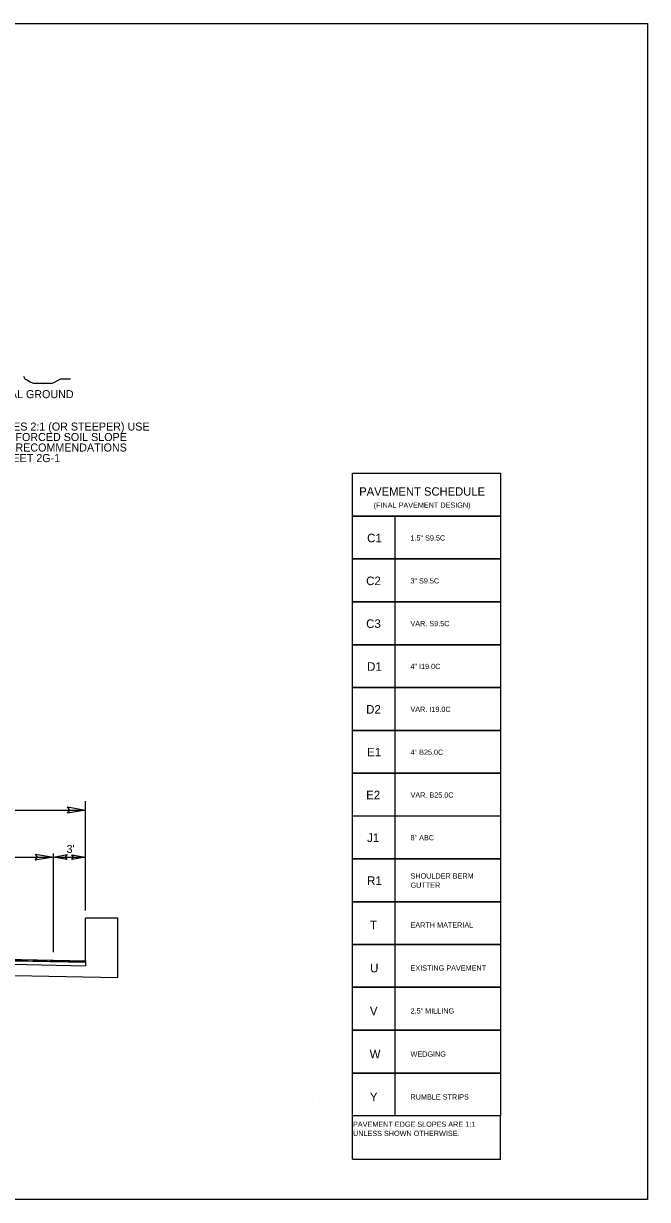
# Model space of a CAD drawing. Extents: x 1548135 to 1549339, y 868664 to 869085.
# Drawn here: x 1548246.7 to 1548305, y 868664.3 to 868774.3 of the extents above; entities that cross this region are included whole.
import ezdxf

# ---------------------------------------------------------------- set-up
doc = ezdxf.new("R2010")
doc.units = 0
for name, color, linetype in [('Default', 7, 'Continuous'), ('P_RDY_TC_Pvmt_Asphalt_Base_Course', 7, 'Continuous'), ('Prop Dimension', 7, 'Continuous'), ('Prop Terminator CELL', 7, 'Continuous'), ('Sheet_Data_Field_CELL', 7, 'Continuous'), ('Typical Grade Point Symbol CELL', 7, 'Continuous'), ('Typical Hinge Slope Interstate CELL', 7, 'Continuous'), ('Typical Shoulder Slope CELL', 7, 'Continuous'), ('Typical Text Grade Point CELL', 7, 'Continuous'), ('Typical Text ID Circle CELL', 7, 'Continuous')]:
    doc.layers.add(name, color=color, linetype=linetype)

msp = doc.modelspace()

# ---------------------------------------------------------------- linework, layer by layer
at = {"layer": 'Default'}
msp.add_lwpolyline([(1548135.05, 868774.32), (1548305.05, 868774.32), (1548305.05, 868664.32), (1548135.05, 868664.32)], close=True, dxfattribs=at)
at = {"layer": 'P_RDY_TC_Pvmt_Asphalt_Base_Course'}
for points in [[(1548250.81, 868701.04), (1548252.5, 868700.75), (1548250.8, 868700.45), (1548251.02, 868700.75)], [(1548247.8, 868696.64), (1548249.49, 868696.35), (1548247.79, 868696.05), (1548248.01, 868696.35)], [(1548250.75, 868696.13), (1548249.49, 868696.35), (1548250.76, 868696.58), (1548250.6, 868696.35)], [(1548251.22, 868696.57), (1548252.49, 868696.35), (1548251.22, 868696.13), (1548251.38, 868696.35)]]:
    msp.add_lwpolyline(points, close=True, dxfattribs=at)
at = {"layer": 'Prop Dimension'}
msp.add_lwpolyline([(1548246.68, 868741.34), (1548246.81, 868741.08), (1548247.07, 868740.95), (1548247.33, 868740.82), (1548247.59, 868740.69), (1548247.85, 868740.69), (1548248.11, 868740.69), (1548248.37, 868740.69), (1548248.63, 868740.69), (1548248.89, 868740.69), (1548249.15, 868740.69), (1548249.41, 868740.69), (1548249.66, 868740.82), (1548249.92, 868740.95), (1548250.18, 868741.08), (1548250.57, 868741.08), (1548250.83, 868741.08), (1548251.09, 868741.08)], dxfattribs=at)
at = {"layer": 'Prop Terminator CELL'}
msp.add_lwpolyline([(1548222.49, 868686.65), (1548237.49, 868686.95), (1548252.49, 868686.65), (1548252.49, 868686.52), (1548247.13, 868686.63), (1548245.81, 868686.66), (1548243.62, 868686.7), (1548237.49, 868686.82), (1548237.49, 868686.82), (1548226.43, 868686.6), (1548222.49, 868686.52)], close=True, dxfattribs=at)
at = {"layer": 'Typical Grade Point Symbol CELL'}
for p, q in [((1548252.49, 868691.35), (1548252.49, 868701.58)), ((1548237.49, 868700.75), (1548252.49, 868700.75)), ((1548249.49, 868687.47), (1548249.49, 868696.7)), ((1548237.49, 868696.35), (1548252.49, 868696.35)), ((1548250.49, 868696.35), (1548252.49, 868696.35))]:
    msp.add_line(p, q, dxfattribs=at)
at = {"layer": 'Typical Hinge Slope Interstate CELL'}
for p, q in [((1548273.7, 868673.74), (1548273.7, 868673.74)), ((1548277.45, 868669.06), (1548277.45, 868672.16)), ((1548277.45, 868668.11), (1548277.45, 868672.12)), ((1548291.3, 868668.07), (1548291.3, 868672.12)), ((1548281.46, 868668.07), (1548277.45, 868668.07)), ((1548291.3, 868668.07), (1548281.46, 868668.07))]:
    msp.add_line(p, q, dxfattribs=at)
msp.add_lwpolyline([(1548277.45, 868732.25), (1548291.29, 868732.25), (1548291.29, 868728.25), (1548277.45, 868728.25)], close=True, dxfattribs=at)
for points in [[(1548281.45, 868724.24), (1548277.45, 868724.24), (1548277.45, 868728.25), (1548291.29, 868728.25), (1548291.29, 868724.24), (1548281.45, 868724.24), (1548281.45, 868728.25)], [(1548281.45, 868720.23), (1548277.45, 868720.23), (1548277.45, 868724.24), (1548291.29, 868724.24), (1548291.29, 868720.23), (1548281.45, 868720.23), (1548281.45, 868724.24)], [(1548281.46, 868716.22), (1548277.45, 868716.22), (1548277.45, 868720.23), (1548291.29, 868720.23), (1548291.29, 868716.22), (1548281.46, 868716.22), (1548281.46, 868720.23)], [(1548281.46, 868712.21), (1548277.45, 868712.21), (1548277.45, 868716.22), (1548291.29, 868716.22), (1548291.29, 868712.21), (1548281.46, 868712.21), (1548281.46, 868716.22)], [(1548281.46, 868708.2), (1548277.45, 868708.2), (1548277.45, 868712.21), (1548291.29, 868712.21), (1548291.29, 868708.2), (1548281.46, 868708.2), (1548281.46, 868712.21)], [(1548281.46, 868704.2), (1548277.45, 868704.2), (1548277.45, 868708.21), (1548291.3, 868708.21), (1548291.3, 868704.2), (1548281.46, 868704.2), (1548281.46, 868708.21)], [(1548281.46, 868704.19), (1548277.45, 868704.19), (1548277.45, 868708.2), (1548291.29, 868708.2), (1548291.29, 868704.19), (1548281.46, 868704.19), (1548281.46, 868708.2)], [(1548281.46, 868700.19), (1548277.45, 868700.19), (1548277.45, 868704.2), (1548291.3, 868704.2), (1548291.3, 868700.19), (1548281.46, 868700.19), (1548281.46, 868704.2)], [(1548281.46, 868696.19), (1548277.45, 868696.19), (1548277.45, 868700.2), (1548291.3, 868700.2), (1548291.3, 868696.19), (1548281.46, 868696.19), (1548281.46, 868700.2)], [(1548281.46, 868696.19), (1548277.45, 868696.19), (1548277.45, 868700.2), (1548291.3, 868700.2), (1548291.3, 868696.19), (1548281.46, 868696.19), (1548281.46, 868700.2)], [(1548281.46, 868692.18), (1548277.45, 868692.18), (1548277.45, 868696.19), (1548291.3, 868696.19), (1548291.3, 868692.18), (1548281.46, 868692.18), (1548281.46, 868696.19)], [(1548281.46, 868688.17), (1548277.45, 868688.17), (1548277.45, 868692.18), (1548291.3, 868692.18), (1548291.3, 868688.17), (1548281.46, 868688.17), (1548281.46, 868692.18)], [(1548281.46, 868684.17), (1548277.45, 868684.17), (1548277.45, 868688.18), (1548291.3, 868688.18), (1548291.3, 868684.17), (1548281.46, 868684.17), (1548281.46, 868688.18)], [(1548281.46, 868680.16), (1548277.45, 868680.16), (1548277.45, 868684.17), (1548291.3, 868684.17), (1548291.3, 868680.16), (1548281.46, 868680.16), (1548281.46, 868684.17)], [(1548281.46, 868676.15), (1548277.45, 868676.15), (1548277.45, 868680.16), (1548291.3, 868680.16), (1548291.3, 868676.15), (1548281.46, 868676.15), (1548281.46, 868680.16)], [(1548281.46, 868672.14), (1548277.45, 868672.14), (1548277.45, 868676.15), (1548291.3, 868676.15), (1548291.3, 868672.14), (1548281.46, 868672.14), (1548281.46, 868676.15)]]:
    msp.add_lwpolyline(points, dxfattribs=at)
at = {"layer": 'Typical Text Grade Point CELL'}
for p, q in [((1548237.49, 868686.82), (1548252.49, 868686.52)), ((1548252.49, 868686.65), (1548252.49, 868686.19)), ((1548237.49, 868686.49), (1548252.49, 868686.19))]:
    msp.add_line(p, q, dxfattribs=at)
at = {"layer": 'Typical Text ID Circle CELL'}
for p, q in [((1548252.49, 868690.67), (1548255.49, 868690.67)), ((1548252.49, 868686.65), (1548252.49, 868690.65)), ((1548255.49, 868690.67), (1548255.49, 868685.09)), ((1548237.49, 868686.95), (1548252.49, 868686.65)), ((1548237.49, 868685.45), (1548255.49, 868685.09))]:
    msp.add_line(p, q, dxfattribs=at)

# ---------------------------------------------------------------- texts
at = {"layer": 'Sheet_Data_Field_CELL'}
msp.add_text('ORIGINAL GROUND', height=0.75, dxfattribs=at).set_placement((1548241.85, 868739.28))
at = {"layer": 'Typical Hinge Slope Interstate CELL'}
for s, height, p in [('FOR FILL SLOPES 2:1 (OR STEEPER) USE', 0.75, (1548238.36, 868736.25)), ('MODIFIED REINFORCED SOIL SLOPE', 0.75, (1548238.36, 868735.27)), ('PER GEOTECH RECOMMENDATIONS', 0.75, (1548238.36, 868734.29)), ('SHOWN ON SHEET 2G-1', 0.75, (1548238.36, 868733.3)), ('PAVEMENT SCHEDULE', 0.784, (1548278.09, 868730.16)), ('(FINAL PAVEMENT DESIGN)', 0.49, (1548279.44, 868729.03)), ('C1', 0.8, (1548278.83, 868725.8)), ('1.5" S9.5C', 0.49, (1548282.88, 868725.96)), ('C2', 0.8, (1548278.74, 868721.79)), ('3" S9.5C', 0.49, (1548282.88, 868721.95)), ('C3', 0.8, (1548278.74, 868717.79)), ('VAR. S9.5C', 0.49, (1548282.88, 868717.95)), ('D1', 0.8, (1548278.83, 868713.78)), ('4" I19.0C', 0.49, (1548282.88, 868713.94)), ('D2', 0.8, (1548278.74, 868709.77)), ('VAR. I19.0C', 0.49, (1548282.88, 868709.93)), ('E1', 0.8, (1548278.83, 868705.77)), ('4" B25.0C', 0.49, (1548282.89, 868705.92)), ('E2', 0.8, (1548278.74, 868701.76)), ('VAR. B25.0C', 0.49, (1548282.89, 868701.91)), ('J1', 0.8, (1548278.83, 868697.76)), ('8" ABC', 0.49, (1548282.89, 868697.92)), ('R1', 0.8, (1548278.83, 868693.75)), ('SHOULDER BERM', 0.49, (1548282.89, 868694.34)), ('GUTTER', 0.49, (1548282.89, 868693.48)), ('T', 0.8, (1548279.1, 868689.6)), ('EARTH MATERIAL', 0.49, (1548282.89, 868689.75)), ('U', 0.8, (1548279.11, 868685.57)), ('EXISTING PAVEMENT', 0.49, (1548282.89, 868685.73)), ('V', 0.8, (1548279.09, 868681.56)), ('2.5" MILLING', 0.49, (1548282.89, 868681.72)), ('W', 0.8, (1548279.07, 868677.53)), ('WEDGING', 0.49, (1548282.89, 868677.68)), ('Y', 0.8, (1548279.09, 868673.52)), ('RUMBLE STRIPS', 0.49, (1548282.89, 868673.67)), ('PAVEMENT EDGE SLOPES ARE 1:1', 0.49, (1548277.51, 868671.12)), ('UNLESS SHOWN OTHERWISE.', 0.49, (1548277.51, 868670.26))]:
    msp.add_text(s, height=height, dxfattribs=at).set_placement(p)
at = {"layer": 'Typical Shoulder Slope CELL'}
msp.add_text("3' ", height=0.75, dxfattribs=at).set_placement((1548250.72, 868696.74))

doc.saveas('drawing.dxf')
